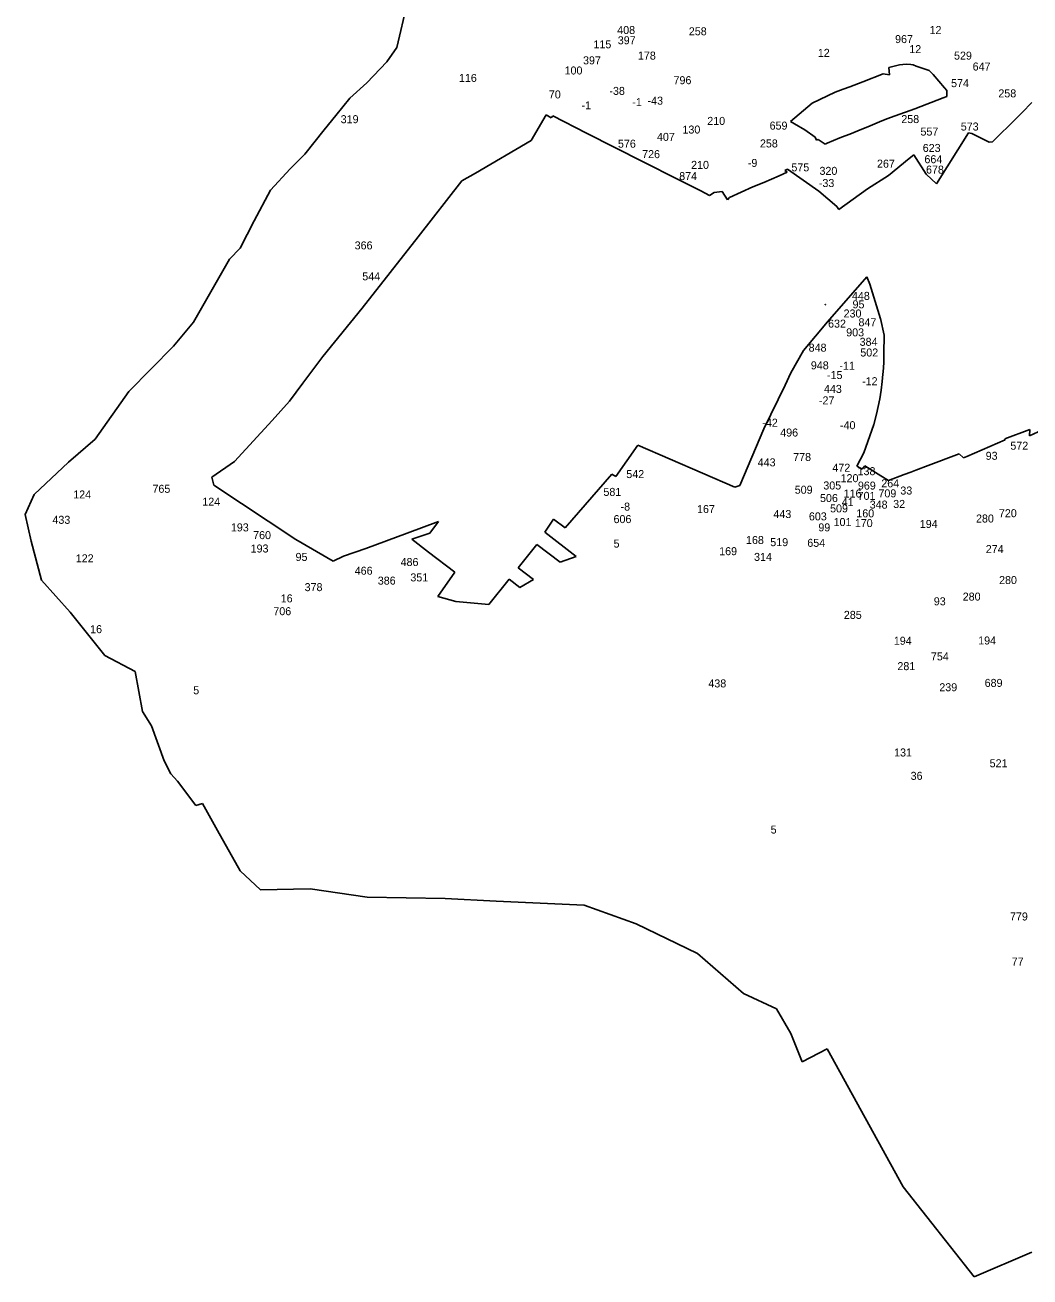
# Model space of a CAD drawing. Extents: x -782977 to -778030, y -975420 to -964838.
# Drawn here: x -781597 to -780729, y -974803 to -973722 of the extents above; entities that cross this region are included whole.
import ezdxf

# ---------------------------------------------------------------- set-up
doc = ezdxf.new("R2010")
doc.units = 0
for name, color, linetype in [('Vrstva 13', 7, 'Continuous'), ('Vrstva 24', 7, 'Continuous'), ('Vrstva 25', 7, 'Continuous')]:
    doc.layers.add(name, color=color, linetype=linetype)

msp = doc.modelspace()

# ---------------------------------------------------------------- linework, layer by layer
at = {"layer": 'Vrstva 13'}
for p, q in [((-781267.09, -973703.17), (-781276.09, -973741.07)), ((-781276.09, -973741.07), (-781284.48, -973753.58)), ((-781284.48, -973753.58), (-781301.77, -973771.58)), ((-780851.07, -973758.53), (-780841.84, -973756.1)), ((-780850.47, -973764.73), (-780851.07, -973758.53)), ((-780841.84, -973756.1), (-780836.2, -973755.55)), ((-780836.2, -973755.55), (-780832.07, -973755.73)), ((-780832.07, -973755.73), (-780830.16, -973756.17)), ((-780830.16, -973756.17), (-780827.63, -973757.32)), ((-780827.63, -973757.32), (-780821.55, -973759.34)), ((-780821.55, -973759.34), (-780816.3, -973761.06)), ((-780884.71, -973775.02), (-780873.7, -973770.7)), ((-780873.7, -973770.7), (-780856.12, -973763.9)), ((-780856.12, -973763.9), (-780850.47, -973764.73)), ((-780816.3, -973761.06), (-780812.737, -973764.538)), ((-780812.737, -973764.538), (-780803.164, -973775.982)), ((-781301.77, -973771.58), (-781316.57, -973785.05)), ((-780917.45, -973789.27), (-780897.47, -973779.79)), ((-780897.47, -973779.79), (-780890.59, -973777.04)), ((-780890.59, -973777.04), (-780884.71, -973775.02)), ((-780803.164, -973775.982), (-780801.035, -973778.294)), ((-780801.035, -973778.294), (-780801.037, -973783.442)), ((-781316.57, -973785.05), (-781328.72, -973799.75)), ((-780936.12, -973805), (-780917.45, -973789.27)), ((-780804.18, -973784.55), (-780828.68, -973794.17)), ((-780804.18, -973784.55), (-780801.037, -973783.442)), ((-780727.68, -973788.73), (-780736.08, -973797.35)), ((-781328.72, -973799.75), (-781338.58, -973812.36)), ((-781147.12, -973799.41), (-781160.02, -973821.44)), ((-781142.79, -973801.81), (-781147.12, -973799.41)), ((-781141.26, -973800.08), (-781142.79, -973801.81)), ((-781112.28, -973815.23), (-781141.26, -973800.08)), ((-780859.06, -973805.46), (-780852.77, -973802.75)), ((-780845.75, -973800.09), (-780852.77, -973802.75)), ((-780828.68, -973794.17), (-780845.75, -973800.09)), ((-780736.08, -973797.35), (-780744.04, -973805.25)), ((-781338.58, -973812.36), (-781355.3, -973833.41)), ((-780936.12, -973805), (-780932.65, -973807.14)), ((-780932.65, -973807.14), (-780923.63, -973812.3)), ((-780923.63, -973812.3), (-780914.73, -973818.57)), ((-780875.96, -973812.21), (-780883.25, -973815.29)), ((-780869.3, -973809.59), (-780875.96, -973812.21)), ((-780859.06, -973805.46), (-780869.3, -973809.59)), ((-780744.04, -973805.25), (-780758.24, -973819.23)), ((-781208.15, -973849.66), (-781160.02, -973821.44)), ((-781063.39, -973839.88), (-781112.28, -973815.23)), ((-780914.73, -973818.57), (-780913.63, -973821.05)), ((-780913.63, -973821.05), (-780912.13, -973820.49)), ((-780912.13, -973820.49), (-780905.98, -973824.74)), ((-780905.98, -973824.74), (-780904.42, -973823.88)), ((-780893.31, -973819.28), (-780904.42, -973823.88)), ((-780883.25, -973815.29), (-780893.31, -973819.28)), ((-780809.83, -973858.82), (-780782.45, -973814.99)), ((-780782.45, -973814.99), (-780779.53, -973815.52)), ((-780779.53, -973815.52), (-780764.44, -973822.97)), ((-780764.44, -973822.97), (-780761.63, -973822.71)), ((-780761.63, -973822.71), (-780761.14, -973821.98)), ((-780758.24, -973819.23), (-780761.14, -973821.98)), ((-781355.3, -973833.41), (-781368, -973845.92)), ((-780829.49, -973833.84), (-780833.6, -973836.91)), ((-780818.89, -973850.69), (-780829.49, -973833.84)), ((-781368, -973845.92), (-781385.03, -973864.28)), ((-781033.6, -973854.99), (-781063.39, -973839.88)), ((-780940.94, -973847.26), (-780938.534, -973846.282)), ((-780938.534, -973846.282), (-780911.45, -973865.32)), ((-780833.6, -973836.91), (-780851.48, -973851.82)), ((-781219.73, -973856.35), (-781257.46, -973904.59)), ((-781208.15, -973849.66), (-781219.73, -973856.35)), ((-781013.52, -973865.09), (-781033.6, -973854.99)), ((-780968.44, -973861.56), (-780959.05, -973857.78)), ((-780959.05, -973857.78), (-780952.35, -973854.86)), ((-780952.35, -973854.86), (-780945.74, -973852.03)), ((-780945.74, -973852.03), (-780938.96, -973848.94)), ((-780938.96, -973848.94), (-780940.94, -973847.26)), ((-780851.48, -973851.82), (-780869.45, -973863.32)), ((-780818.89, -973850.69), (-780809.83, -973858.82)), ((-781385.03, -973864.28), (-781399.06, -973890.98)), ((-781006.08, -973868.86), (-781013.52, -973865.09)), ((-781002.01, -973866.41), (-781006.08, -973868.86)), ((-780994.98, -973865.5), (-781002.01, -973866.41)), ((-780990.29, -973872.74), (-780994.98, -973865.5)), ((-780988.8, -973870.71), (-780968.44, -973861.56)), ((-780911.45, -973865.32), (-780895.88, -973878.42)), ((-780894.19, -973880.97), (-780869.45, -973863.32)), ((-780990.29, -973872.74), (-780988.8, -973870.71)), ((-780894.19, -973880.97), (-780895.88, -973878.42)), ((-781399.06, -973890.98), (-781411.26, -973914.44)), ((-781257.46, -973904.59), (-781305.86, -973966.38)), ((-781411.26, -973914.44), (-781420.55, -973924.04)), ((-781420.55, -973924.04), (-781451.64, -973978.55)), ((-780903.94, -973978.09), (-780870.04, -973939.34)), ((-780870.04, -973939.34), (-780867.52, -973945.69)), ((-780867.52, -973945.69), (-780858.21, -973975.48)), ((-781305.86, -973966.38), (-781339.81, -974008.18)), ((-780855.12, -973989.72), (-780858.26, -973975.27)), ((-781451.64, -973978.55), (-781468.82, -973999.09)), ((-780924.84, -974002.87), (-780903.94, -973978.09)), ((-780855.12, -973989.72), (-780855.37, -974005.55)), ((-781468.82, -973999.09), (-781507.46, -974038.25)), ((-781339.81, -974008.18), (-781357.03, -974031.23)), ((-780935.85, -974022.14), (-780924.84, -974002.87)), ((-780855.37, -974005.55), (-780855.49, -974013.52)), ((-780855.49, -974013.52), (-780856.07, -974021.24)), ((-780940.74, -974032.74), (-780935.85, -974022.14)), ((-780856.95, -974029.54), (-780857.75, -974037.26)), ((-780856.29, -974023.35), (-780856.95, -974029.54)), ((-780856.07, -974021.24), (-780856.29, -974023.35)), ((-781507.46, -974038.25), (-781536.54, -974079.45)), ((-781357.03, -974031.23), (-781368.76, -974046.73)), ((-780958.99, -974070.48), (-780940.74, -974032.74)), ((-780858.98, -974044.76), (-780857.75, -974037.26)), ((-781368.76, -974046.73), (-781383.74, -974063.45)), ((-780861.77, -974057.76), (-780858.98, -974044.76)), ((-780863.94, -974066.89), (-780861.77, -974057.76)), ((-781383.74, -974063.45), (-781416.05, -974098.73)), ((-780979.71, -974119.51), (-780958.99, -974070.48)), ((-780863.94, -974066.89), (-780872.78, -974091.36)), ((-780729.28, -974071.13), (-780750.9, -974079.07)), ((-780729.57, -974076.59), (-780707.15, -974066.25)), ((-780729.28, -974071.13), (-780729.57, -974076.59)), ((-781536.54, -974079.45), (-781559.52, -974099.38)), ((-781086.74, -974111.77), (-781067.85, -974084.66)), ((-781067.85, -974084.66), (-780984.14, -974120.84)), ((-780777.03, -974091.45), (-780750.54, -974080.02)), ((-780750.54, -974080.02), (-780750.9, -974079.07)), ((-780872.78, -974091.36), (-780878.75, -974102.87)), ((-780817.29, -974102.29), (-780790.28, -974092.03)), ((-780790.28, -974092.03), (-780786.57, -974095.6)), ((-780786.57, -974095.6), (-780783.66, -974094.36)), ((-780783.66, -974094.36), (-780777.03, -974091.45)), ((-781559.52, -974099.38), (-781589.08, -974127.38)), ((-781416.05, -974098.73), (-781435.62, -974112.29)), ((-780878.75, -974102.87), (-780874.01, -974105.42)), ((-780874.01, -974105.42), (-780871.83, -974102.58)), ((-780871.83, -974102.58), (-780858.15, -974111.17)), ((-780832.24, -974108.11), (-780827.82, -974106.29)), ((-780827.82, -974106.29), (-780817.29, -974102.29)), ((-781435.62, -974112.29), (-781433.96, -974119.2)), ((-781130.67, -974155.97), (-781090.25, -974109.68)), ((-781090.25, -974109.68), (-781086.74, -974111.77)), ((-780858.15, -974111.17), (-780851.38, -974115.17)), ((-780851.38, -974115.17), (-780838.02, -974110.07)), ((-780838.02, -974110.07), (-780832.24, -974108.11)), ((-781589.08, -974127.38), (-781597, -974144.63)), ((-781433.96, -974119.2), (-781363.32, -974166.2)), ((-780984.14, -974120.84), (-780979.71, -974119.51)), ((-781597, -974144.63), (-781591.66, -974167.46)), ((-781148.15, -974159.95), (-781140.66, -974148.58)), ((-781140.66, -974148.58), (-781130.67, -974155.97)), ((-781302.87, -974173.89), (-781267.08, -974160.66)), ((-781267.08, -974160.66), (-781239.97, -974150.67)), ((-781247.51, -974160.66), (-781263.03, -974165.99)), ((-781239.97, -974150.67), (-781247.51, -974160.66)), ((-781121.04, -974180.96), (-781148.15, -974159.95)), ((-781591.66, -974167.46), (-781582.88, -974201.2)), ((-781363.32, -974166.2), (-781330.85, -974184.91)), ((-781263.03, -974165.99), (-781248.71, -974177.05)), ((-781171.23, -974190.49), (-781155.18, -974170.61)), ((-781155.18, -974170.61), (-781135, -974185.75)), ((-781330.85, -974184.91), (-781321.98, -974180.52)), ((-781321.98, -974180.52), (-781302.87, -974173.89)), ((-781248.71, -974177.05), (-781225.99, -974194.49)), ((-781135, -974185.75), (-781121.04, -974180.96)), ((-781157.83, -974200.79), (-781171.23, -974190.49)), ((-781582.88, -974201.2), (-781558.08, -974228.87)), ((-781225.99, -974194.49), (-781240.62, -974215.31)), ((-781196.48, -974222.24), (-781179.08, -974200.54)), ((-781179.08, -974200.54), (-781169.75, -974207.58)), ((-781169.75, -974207.58), (-781157.83, -974200.79)), ((-781240.62, -974215.31), (-781225.12, -974219.69)), ((-781225.12, -974219.69), (-781196.48, -974222.24)), ((-781558.08, -974228.87), (-781527.99, -974266.3)), ((-781527.99, -974266.3), (-781501.85, -974280.23)), ((-781501.85, -974280.23), (-781495.52, -974314.73)), ((-781495.52, -974314.73), (-781487.84, -974327.19)), ((-781487.84, -974327.19), (-781476.96, -974357.36)), ((-781476.96, -974357.36), (-781471.17, -974368.7)), ((-781471.17, -974368.7), (-781465.29, -974374.98)), ((-781465.29, -974374.98), (-781449.46, -974395.96)), ((-781449.46, -974395.96), (-781443.73, -974394.11)), ((-781443.73, -974394.11), (-781430.92, -974417.6)), ((-781430.92, -974417.6), (-781411.24, -974452.44)), ((-781411.24, -974452.44), (-781393.75, -974468.72)), ((-781393.75, -974468.72), (-781350.84, -974467.91)), ((-781350.84, -974467.91), (-781301.48, -974475.18)), ((-781301.48, -974475.18), (-781234.27, -974476.19)), ((-781234.27, -974476.19), (-781190.19, -974478.48)), ((-781190.19, -974478.48), (-781114.34, -974482.14)), ((-781114.34, -974482.14), (-781069.19, -974498.22)), ((-781069.19, -974498.22), (-781016.32, -974523.65)), ((-781016.32, -974523.65), (-780976.66, -974558.23)), ((-780976.66, -974558.23), (-780948.18, -974571.46)), ((-780948.18, -974571.46), (-780935.78, -974592.82)), ((-780935.78, -974592.82), (-780925.82, -974617.23)), ((-780925.82, -974617.23), (-780904.46, -974606.04)), ((-780904.46, -974606.04), (-780838.79, -974725.47)), ((-780838.79, -974725.47), (-780777.37, -974803.19)), ((-780777.37, -974803.19), (-780727.54, -974781.83))]:
    msp.add_line(p, q, dxfattribs=at)
at = {"layer": 'Vrstva 25'}
msp.add_circle((-780905.939, -973963.27), 0.175, dxfattribs=at)

# ---------------------------------------------------------------- texts
at = {"layer": 'Vrstva 24'}
for s, p in [('408', (-781085.657, -973729.492)), ('258', (-781023.822, -973730.592)), ('12', (-780815.949, -973729.512)), ('115', (-781106.179, -973741.832)), ('397', (-781085.185, -973738.362)), ('967', (-780845.721, -973737.332)), ('397', (-781115.175, -973755.702)), ('178', (-781067.762, -973751.582)), ('12', (-780912.449, -973749.222)), ('12', (-780833.439, -973746.022)), ('529', (-780794.819, -973751.612)), ('100', (-781131.12, -973764.442)), ('647', (-780778.748, -973761.042)), ('116', (-781222.335, -973770.902)), ('796', (-781037.031, -973772.852)), ('574', (-780797.362, -973775.382)), ('70', (-781144.695, -973785.142)), ('-38', (-781092.406, -973782.085)), ('258', (-780756.542, -973784.222)), ('-1', (-781116.464, -973794.581)), ('-1', (-781072.674, -973791.765)), ('-43', (-781059.48, -973790.545)), ('319', (-781324.442, -973806.522)), ('210', (-781007.898, -973807.992)), ('258', (-780840.342, -973806.432)), ('130', (-781029.318, -973815.472)), ('659', (-780954.065, -973812.072)), ('557', (-780823.799, -973817.242)), ('573', (-780788.999, -973812.852)), ('576', (-781085.025, -973827.682)), ('407', (-781051.334, -973821.792)), ('258', (-780962.422, -973827.482)), ('623', (-780821.849, -973831.362)), ('726', (-781064.145, -973836.712)), ('664', (-780820.388, -973841.112)), ('210', (-781021.848, -973846.002)), ('-9', (-780972.878, -973844.305)), ('575', (-780935.239, -973848.112)), ('320', (-780910.995, -973851.152)), ('267', (-780861.345, -973844.952)), ('678', (-780819.005, -973850.072)), ('874', (-781032.152, -973855.682)), ('-33', (-780911.566, -973861.705)), ('366', (-781312.385, -973915.552)), ('544', (-781305.788, -973942.262)), ('448', (-780882.977, -973959.172)), ('95', (-780882.453, -973966.432)), ('632', (-780903.589, -973983.112)), ('230', (-780890.175, -973974.362)), ('847', (-780877.322, -973981.942)), ('903', (-780887.921, -973990.672)), ('848', (-780920.365, -974003.862)), ('384', (-780876.335, -973998.822)), ('502', (-780875.724, -974008.062)), ('948', (-780918.451, -974019.162)), ('-11', (-780893.833, -974019.505)), ('-15', (-780904.53, -974027.545)), ('-12', (-780874.22, -974032.875)), ('443', (-780907.147, -974039.542)), ('-27', (-780911.474, -974049.435)), ('-42', (-780960.34, -974068.725)), ('496', (-780944.898, -974077.192)), ('-40', (-780893.282, -974070.855)), ('572', (-780746.189, -974088.562)), ('778', (-780933.705, -974098.312)), ('93', (-780767.493, -974097.282)), ('542', (-781077.805, -974113.082)), ('443', (-780964.367, -974102.972)), ('472', (-780899.851, -974107.582)), ('138', (-780878.105, -974110.592)), ('305', (-780907.684, -974122.932)), ('120', (-780892.768, -974116.622)), ('969', (-780877.821, -974123.022)), ('264', (-780857.631, -974121.082)), ('124', (-781555.389, -974130.702)), ('765', (-781486.975, -974125.802)), ('581', (-781097.575, -974128.482)), ('509', (-780932.371, -974126.602)), ('506', (-780910.541, -974133.772)), ('116', (-780890.165, -974129.892)), ('701', (-780878.074, -974131.892)), ('709', (-780860.097, -974129.752)), ('33', (-780841.176, -974127.302)), ('124', (-781443.949, -974136.932)), ('-8', (-781082.78, -974141.185)), ('167', (-781016.749, -974143.302)), ('509', (-780901.851, -974142.712)), ('41', (-780891.842, -974137.242)), ('348', (-780867.635, -974139.432)), ('32', (-780847.356, -974138.892)), ('433', (-781573.355, -974152.602)), ('606', (-781088.837, -974151.972)), ('443', (-780950.787, -974147.592)), ('603', (-780920.141, -974149.632)), ('101', (-780898.811, -974154.532)), ('170', (-780880.495, -974155.402)), ('160', (-780879.184, -974147.022)), ('194', (-780824.385, -974156.162)), ('280', (-780775.845, -974151.462)), ('720', (-780756.071, -974146.892)), ('193', (-781419.261, -974159.152)), ('760', (-781400.047, -974165.812)), ('99', (-780911.979, -974159.132)), ('193', (-781402.201, -974177.392)), ('5', (-781088.78, -974173.112)), ('168', (-780974.451, -974170.062)), ('519', (-780953.492, -974171.892)), ('654', (-780921.531, -974172.492)), ('274', (-780767.412, -974177.842)), ('122', (-781553.215, -974185.882)), ('95', (-781363.413, -974184.672)), ('486', (-781272.711, -974189.072)), ('169', (-780997.619, -974179.692)), ('314', (-780967.489, -974184.622)), ('466', (-781312.328, -974196.572)), ('378', (-781355.589, -974210.762)), ('386', (-781292.409, -974205.112)), ('351', (-781264.265, -974202.352)), ('280', (-780755.915, -974204.622)), ('16', (-781376.216, -974220.462)), ('280', (-780787.315, -974218.922)), ('706', (-781382.587, -974231.552)), ('93', (-780812.293, -974222.992)), ('285', (-780889.962, -974234.712)), ('16', (-781540.796, -974247.062)), ('194', (-780846.805, -974257.072)), ('194', (-780773.955, -974256.832)), ('754', (-780814.792, -974270.582)), ('281', (-780843.715, -974279.002)), ('438', (-781006.955, -974293.922)), ('239', (-780807.529, -974297.222)), ('689', (-780768.375, -974293.482)), ('5', (-781451.79, -974299.852)), ('131', (-780846.569, -974353.592)), ('521', (-780764.065, -974362.902)), ('36', (-780832.273, -974373.752)), ('5', (-780953.16, -974420.152)), ('779', (-780746.502, -974495.232)), ('77', (-780744.989, -974534.162))]:
    msp.add_text(s, height=6.912, dxfattribs=at).set_placement(p)

doc.saveas('drawing.dxf')
